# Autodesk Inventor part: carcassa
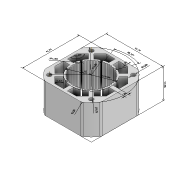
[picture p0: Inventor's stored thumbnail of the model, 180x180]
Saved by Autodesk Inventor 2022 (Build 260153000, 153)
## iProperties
Created: 2021-04
Part Number: carcassa
Material: Generico
Document SubType Name: Modeling
Designer: admin
Density: 1 g/cm^3
Appearance: Default
Author: admin
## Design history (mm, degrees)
node "Annotazioni"
  node "Quota lineare 1" dims "d4" = 41.7899 (derived)
  node "Quota lineare 2" dims "d7" = 41.7899 (derived)
  node "Quota diametro 1" dims "d9" = 29 (derived)
  node "Quota radiale 1" dims "d11" = 13 (derived)
  node "Quota diametro 2" dims "d13" = 3 (derived)
  node "Quota lineare 3" dims "d16" = 1.89495 (derived)
  node "Quota lineare 4" dims "d19" = 2.8 (derived)
  node "Quota angolare 1" dims "d22" = 135 deg (derived)
  node "Quota diametro 3" dims "d24" = 49.7899 (derived)
  node "Quota lineare 5" dims "d26" = 22 (derived)
  node "Quota lineare 6" dims "d28" = 21.92031 (derived)
  node "Quota radiale 2" dims "d30" = 2.89495 (derived)
  node "Quota diametro 4" dims "d32" = 1 (derived)
  node "Quota angolare 2" dims "d35" = 6.77054 (derived)
  node "Quota lineare 7" dims "d38" = 4.56774 (derived)
sketch "Schizzo1"
  geometry: L1 (-20.895, -12.649)-(-20.895, 12.649); L2 (-14.432, 1.4)-(-19, 1.4); L3 (-13.677, 4.815)-(-12.262, 4.317); L4 (-19, 7.87)-(-19, 1.4); L5 (20.895, 12.649)-(20.895, -12.649); L6 (14.432, -1.4)-(19, -1.4); L7 (13.677, -4.815)-(12.262, -4.317); L8 (19, -7.87)-(19, -1.4); L9 (-14.425, 12.445)-(-11.195, 9.215); L10 (-11.723, 5.618)-(-13.076, 6.266); L11 (-14.425, 12.445)-(-19, 7.87); L12 (1.4, 14.432)-(1.4, 19); L13 (7.87, 19)-(1.4, 19); L14 (4.815, 13.677)-(4.317, 12.262); L15 (5.618, 11.723)-(6.266, 13.076); L16 (12.445, 14.425)-(7.87, 19); L17 (-1.4, 19)-(-1.4, 14.432); L18 (-12.649, 20.895)-(12.649, 20.895); L19 (19, 1.4)-(14.432, 1.4); L20 (-4.815, -13.677)-(-4.317, -12.262); L21 (-5.618, -11.723)-(-6.266, -13.076); L22 (-12.445, -14.425)-(-9.215, -11.195); L23 (-1.4, -14.432)-(-1.4, -19); L24 (-7.87, -19)-(-1.4, -19); L25 (-12.445, -14.425)-(-7.87, -19); L26 (-19, -1.4)-(-19, -7.87); L27 (-19, -1.4)-(-14.432, -1.4); L28 (-12.262, -4.317)-(-13.677, -4.815); L29 (-9.215, 11.195)-(-12.445, 14.425); L30 (-6.266, 13.076)-(-5.618, 11.723); L31 (-7.87, 19)-(-12.445, 14.425); L32 (-1.4, 19)-(-7.87, 19); L33 (12.445, 14.425)-(9.215, 11.195); L34 (11.195, 9.215)-(14.425, 12.445); L35 (13.076, 6.266)-(11.723, 5.618); L36 (19, 7.87)-(14.425, 12.445); L37 (12.262, 4.317)-(13.677, 4.815); L38 (19, 1.4)-(19, 7.87); L39 (11.723, -5.618)-(13.076, -6.266); L40 (12.649, -20.895)-(-12.649, -20.895); L41 (14.425, -12.445)-(19, -7.87); L42 (14.425, -12.445)-(11.195, -9.215); L43 (6.266, -13.076)-(5.618, -11.723); L44 (4.317, -12.262)-(4.815, -13.677); L45 (1.4, -19)-(1.4, -14.432); L46 (1.4, -19)-(7.87, -19); L47 (7.87, -19)-(12.445, -14.425); L48 (9.215, -11.195)-(12.445, -14.425); L49 (-4.317, 12.262)-(-4.815, 13.677); L50 (-11.195, -9.215)-(-14.425, -12.445); L51 (-13.076, -6.266)-(-11.723, -5.618); L52 (-19, -7.87)-(-14.425, -12.445); C1 r 1.5 at (-15.5, 15.5); C2 r 1.5 at (15.5, 15.5); C3 r 1.5 at (15.5, -15.5); C4 r 1.5 at (-15.5, -15.5); A1 r 0.5 centre (-12.897, 1.629) between (-12.825, 2.124) and (-12.951, 1.132); A2 r 0.5 centre (-12.592, 3.233) between (-12.458, 3.715) and (-12.707, 2.746); A3 r 13 centre (0, 0) between (-12.262, 4.317) and (-12.458, 3.715); A4 r 14.5 centre (0, 0) between (-13.677, 4.815) and (-14.432, 1.4); A5 r 13 centre (0, 0) between (-12.707, 2.746) and (-12.825, 2.124); A6 r 13 centre (0, 0) between (12.951, -1.132) and (12.99, -0.5); A7 r 0.5 centre (12.897, -1.629) between (12.825, -2.124) and (12.951, -1.132); A8 r 13 centre (0, 0) between (12.707, -2.746) and (12.825, -2.124); A9 r 0.5 centre (12.592, -3.233) between (12.458, -3.715) and (12.707, -2.746); A10 r 14.5 centre (0, 0) between (13.677, -4.815) and (14.432, -1.4); A11 r 13 centre (0, 0) between (12.262, -4.317) and (12.458, -3.715); A12 r 0.5 centre (-10.272, 7.968) between (-9.958, 8.357) and (-10.571, 7.567); A13 r 13 centre (0, 0) between (-9.539, 8.832) and (-9.958, 8.357); A14 r 13 centre (0, 0) between (-10.571, 7.567) and (-10.927, 7.043); A15 r 13 centre (0, 0) between (-11.436, 6.182) and (-11.723, 5.618); A16 r 0.5 centre (-11.19, 6.618) between (-10.927, 7.043) and (-11.436, 6.182); A17 r 2.895 centre (-18, 12.649) between (-20.369, 14.314) and (-20.895, 12.649); A18 r 14.5 centre (0, 0) between (-11.195, 9.215) and (-13.076, 6.266); A19 r 0.5 centre (1.629, 12.897) between (2.124, 12.825) and (1.132, 12.951); A20 r 13 centre (0, 0) between (2.746, 12.707) and (2.124, 12.825); A21 r 0.5 centre (3.233, 12.592) between (3.715, 12.458) and (2.746, 12.707); A22 r 14.5 centre (0, 0) between (4.815, 13.677) and (1.4, 14.432); A23 r 13 centre (0, 0) between (4.317, 12.262) and (3.715, 12.458); A24 r 13 centre (0, 0) between (6.182, 11.436) and (5.618, 11.723); A25 r 0.5 centre (6.618, 11.19) between (7.043, 10.927) and (6.182, 11.436); A26 r 13 centre (0, 0) between (7.567, 10.571) and (7.043, 10.927); A27 r 0.5 centre (7.968, 10.272) between (8.357, 9.958) and (7.567, 10.571); A28 r 14.5 centre (0, 0) between (9.215, 11.195) and (6.266, 13.076); A29 r 13 centre (0, 0) between (1.132, 12.951) and (0.5, 12.99); A30 r 0.5 centre (0, -13) between (-0.5, -12.99) and (0.5, -12.99); A31 r 13 centre (0, 0) between (-1.132, -12.951) and (-0.5, -12.99); A32 r 0.5 centre (-1.629, -12.897) between (-2.124, -12.825) and (-1.132, -12.951); A33 r 13 centre (0, 0) between (-2.746, -12.707) and (-2.124, -12.825); A34 r 0.5 centre (-3.233, -12.592) between (-3.715, -12.458) and (-2.746, -12.707); A35 r 13 centre (0, 0) between (-4.317, -12.262) and (-3.715, -12.458); A36 r 14.5 centre (0, 0) between (-4.815, -13.677) and (-1.4, -14.432); A37 r 14.5 centre (0, 0) between (-9.215, -11.195) and (-6.266, -13.076); A38 r 0.5 centre (-9.192, -9.192) between (-9.539, -8.832) and (-8.832, -9.539); A39 r 13 centre (0, 0) between (-8.832, -9.539) and (-8.357, -9.958); A40 r 0.5 centre (-7.968, -10.272) between (-8.357, -9.958) and (-7.567, -10.571); A41 r 13 centre (0, 0) between (-7.567, -10.571) and (-7.043, -10.927); A42 r 0.5 centre (-6.618, -11.19) between (-7.043, -10.927) and (-6.182, -11.436); A43 r 13 centre (0, 0) between (-6.182, -11.436) and (-5.618, -11.723); A44 r 0.5 centre (-13, 0) between (-12.99, 0.5) and (-12.99, -0.5); A45 r 13 centre (0, 0) between (-12.99, -0.5) and (-12.951, -1.132); A46 r 0.5 centre (-12.897, -1.629) between (-12.951, -1.132) and (-12.825, -2.124); A47 r 13 centre (0, 0) between (-12.825, -2.124) and (-12.707, -2.746); A48 r 0.5 centre (-12.592, -3.233) between (-12.707, -2.746) and (-12.458, -3.715); A49 r 13 centre (0, 0) between (-12.458, -3.715) and (-12.262, -4.317); A50 r 14.5 centre (0, 0) between (-14.432, -1.4) and (-13.677, -4.815); A51 r 13 centre (0, 0) between (-12.951, 1.132) and (-12.99, 0.5); A52 r 2.895 centre (-12.649, 18) between (-12.649, 20.895) and (-14.314, 20.369); A53 r 24.895 centre (0, 0) between (-14.314, 20.369) and (-20.369, 14.314); A54 r 13 centre (0, 0) between (-8.357, 9.958) and (-8.832, 9.539); A55 r 0.5 centre (-7.968, 10.272) between (-7.567, 10.571) and (-8.357, 9.958); A56 r 13 centre (0, 0) between (-7.043, 10.927) and (-7.567, 10.571); A57 r 0.5 centre (-6.618, 11.19) between (-6.182, 11.436) and (-7.043, 10.927); A58 r 13 centre (0, 0) between (-5.618, 11.723) and (-6.182, 11.436); A59 r 14.5 centre (0, 0) between (-6.266, 13.076) and (-9.215, 11.195); A60 r 0.5 centre (-9.192, 9.192) between (-8.832, 9.539) and (-9.539, 8.832); A61 r 13 centre (0, 0) between (8.832, 9.539) and (8.357, 9.958); A62 r 2.895 centre (12.649, 18) between (14.314, 20.369) and (12.649, 20.895); A63 r 24.895 centre (0, 0) between (20.369, 14.314) and (14.314, 20.369); A64 r 2.895 centre (18, 12.649) between (20.895, 12.649) and (20.369, 14.314)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; 2 further points
  constraints: 232 point on circle, 120 centre point, 104 end point
extrude "Estrusione1" new body sketch "Schizzo1" distance "d0" = 22; taper "d1" = 0 deg
node "Asse di lavoro1"
node "Asse di lavoro2"
node "Solido1"
other parameters: "d10" = 51.03729 (derived), "d12" = -15.82863 (derived), "d14" = 4.55417 (derived), "d15" = 3.28187 (derived), "d17" = 6.40878 (derived), "d18" = 3.59122 (derived), "d2" = 7.50196 (derived), "d20" = 7.89909 (derived), "d21" = 4.0191 (derived), "d23" = 0 (derived), "d25" = 4.38843 (derived), "d27" = 22.45029 (derived), "d29" = 21.64521 (derived), "d3" = 2.12909 (derived), "d31" = 1.97591 (derived), "d33" = 5.4843 (derived), "d34" = 9.53844 (derived), "d36" = 0 (derived), "d5" = 2.26744 (derived), "d6" = 6.90241 (derived), "d8" = 35.30076 (derived)
